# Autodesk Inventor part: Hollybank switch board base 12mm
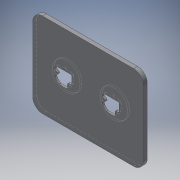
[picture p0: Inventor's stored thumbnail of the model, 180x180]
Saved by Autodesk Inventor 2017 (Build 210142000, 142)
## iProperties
Created: 2015-12
Part Number: Hollybank switch board base 12mm
Material: Generic
Document SubType Name: Modeling
Designer: Designer
Density: 1 g/cm^3
Appearance: Default
Author: Designer
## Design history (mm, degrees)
sketch "Sketch1"
  geometry: L1 (-57, 68.367)-(23, 68.367); L2 (33, 58.367)-(33, -21.633); L3 (23, -31.633)-(-57, -31.633); L4 (-67, -21.633)-(-67, 58.367); L5 (-5, -5)-(-5, 5.367); L6 (-2, 8.367)-(5, 8.367); L7 (8, 11.367)-(8, 33.367); L8 (-39.45, 36.367)-(5, 36.367); L9 (-36.434, 15.879)-(-43.759, 10.649); L10 (-36.443, 20.769)-(-43.792, 25.973); L11 (-40, 13.333)-(-40, 13.33); L12 (-30.528, -8)-(-8, -8); L13 (188, 148.367)-(-72, 148.367); L14 (-112, 108.367)-(-112, -71.633); L15 (-72, -111.633)-(188, -111.633); L16 (228, -71.633)-(228, 108.367); L17 (188, 148.367)-(228, 148.367); L18 (228, 108.367)-(228, 148.367); L19 (228, -71.633)-(228, -111.633); L20 (183, -111.633)-(228, -111.633); L21 (-72, -111.633)-(-112, -111.633); L22 (-112, -111.633)-(-112, -71.633); L23 (-72, 148.367)-(-112, 148.367); L24 (-112, 108.367)-(-112, 148.367); L25 (109.566, 15.879)-(102.241, 10.649); L26 (154, 11.367)-(154, 33.367); L27 (115.472, -8)-(138, -8); L28 (179, 58.367)-(179, -21.633); L29 (169, -31.633)-(89, -31.633); L30 (106, 13.333)-(106, 13.33); L31 (141, -5)-(141, 5.367); L32 (144, 8.367)-(151, 8.367); L33 (89, 68.367)-(169, 68.367); L34 (106.55, 36.367)-(151, 36.367); L35 (79, -21.633)-(79, 58.367); L36 (109.557, 20.769)-(102.208, 25.973); C1 r 1.5 at (-14.993, 41.367); C2 r 1.5 at (-40, 18.33); C3 r 1.5 at (0, 0); C4 r 1.5 at (106, 18.33); C5 r 1.5 at (146, 0); C6 r 1.5 at (131.007, 41.367); A1 r 30 centre (-17, 18.367) between (-41.944, 35.033) and (-44.842, 29.539); A2 r 30 centre (-17, 18.367) between (-44.795, 7.079) and (-32.031, -7.596); A3 r 10 centre (-57, 58.367) between (-57, 68.367) and (-67, 58.367); A4 r 10 centre (23, 58.367) between (33, 58.367) and (23, 68.367); A5 r 10 centre (23, -21.633) between (23, -31.633) and (33, -21.633); A6 r 10 centre (-57, -21.633) between (-67, -21.633) and (-57, -31.633); A7 r 3 centre (-38.177, 18.321) between (-36.434, 15.879) and (-36.443, 20.769); A8 r 3 centre (5, 11.367) between (5, 8.367) and (8, 11.367); A9 r 3 centre (-2, 5.367) between (-2, 8.367) and (-5, 5.367); A10 r 3 centre (-8, -5) between (-8, -8) and (-5, -5); A11 r 3 centre (-42.016, 8.208) between (-43.759, 10.649) and (-44.795, 7.079); A12 r 3 centre (-42.058, 28.422) between (-44.842, 29.539) and (-43.792, 25.973); A13 r 3 centre (-39.45, 33.367) between (-39.45, 36.367) and (-41.944, 35.033); A14 r 3 centre (-30.528, -5) between (-32.031, -7.596) and (-30.528, -8); A15 r 3 centre (5, 33.367) between (8, 33.367) and (5, 36.367); A16 r 30 centre (129, 18.367) between (101.205, 7.079) and (113.969, -7.596); A17 r 3 centre (138, -5) between (138, -8) and (141, -5); A18 r 3 centre (144, 5.367) between (144, 8.367) and (141, 5.367); A19 r 3 centre (151, 11.367) between (151, 8.367) and (154, 11.367); A20 r 10 centre (169, -21.633) between (169, -31.633) and (179, -21.633); A21 r 10 centre (89, -21.633) between (79, -21.633) and (89, -31.633); A22 r 3 centre (151, 33.367) between (154, 33.367) and (151, 36.367); A23 r 10 centre (169, 58.367) between (179, 58.367) and (169, 68.367); A24 r 10 centre (89, 58.367) between (89, 68.367) and (79, 58.367); A25 r 30 centre (129, 18.367) between (104.056, 35.033) and (101.158, 29.539); A26 r 3 centre (115.472, -5) between (113.969, -7.596) and (115.472, -8); A27 r 3 centre (103.984, 8.208) between (102.241, 10.649) and (101.205, 7.079); A28 r 3 centre (107.823, 18.321) between (109.566, 15.879) and (109.557, 20.769); A29 r 3 centre (103.942, 28.422) between (101.158, 29.539) and (102.208, 25.973); A30 r 3 centre (106.55, 33.367) between (106.55, 36.367) and (104.056, 35.033); 24 further points
  constraints: 72 end point, 68 point on circle, 48 tangent, 46 point on line, 36 centre point, 18 equal radius, 16 perpendicular, 7 equal length, 4 horizontal, 2 coincident
  dimensions: "d4" = 3 diameter of C2; "d5" = 3 diameter of C1; "d7" = 100 distance of point (-67, -31.633) point (-67, 68.367); "d8" = 100 distance of point (-67, 68.367) point (33, 68.367); "d17" = 5 distance from line of point (0, 0) L5; "d19" = 25 distance between parallel lines of L2 L7; "d23" = 34 distance of C1.centre C2.centre; "d24" = 44 distance of C1.centre C3.centre; "d25" = 44 distance of point (0, 0) C2.centre; "d26" = 32 distance between parallel lines of L8 L1; "d27" = 47.99344 distance from line of L2 C1.centre; "d28" = 33 distance from line of L2 point (0, 0); "d29" = 27 distance from line of C2.centre L4 (derived); "d30" = 49.96369 distance from line of L3 C2.centre; "d31" = 31.63338 distance from line of L3 C3.centre (derived); "d32" = 30 radius of A2; "d33" = 30 radius of A1; "d34" = 41 distance from line of L7 point (-33, 18.33); "d35" = 8 distance from line of L12 point (0, 0); "d36" = 23.63338 distance between parallel lines of L3 L12 (derived); "d37" = 10 radius of A3; "d40" = 3 radius of A7; "d41" = 3 radius of A8; "d42" = 3 radius of A15; "d61" = 24.98415 distance from line of L4 A11.centre; "d62" = 39.84089 distance from line of L3 A11.centre; "d63" = 28.82318 distance from line of L4 A7.centre; "d64" = 49.95389 distance from line of L3 A7.centre; "d65" = 27.55006 distance from line of L4 A13.centre; "d66" = 28 distance from line of L2 A15.centre; "d67" = 35 distance from line of A15.centre L1; "d68" = 3 diameter of C3; "d69" = 340 distance of L17.end L23.end; "d70" = 260 distance of L19.end L17.end; "d72" = 45 distance between parallel lines of L14 L4; "d117" = 28 distance from line of L2 A8.centre (derived); "d118" = 43 distance from line of L3 A8.centre; "d119" = 3 diameter of C4; "d120" = 3 diameter of C6; "d121" = 100 distance of point (79, -31.633) point (79, 68.367); "d122" = 100 distance of point (79, 68.367) point (179, 68.367); "d123" = 5 distance from line of point (146, 0) L31; "d124" = 25 distance between parallel lines of L28 L26; "d125" = 34 distance of C6.centre C4.centre; "d126" = 44 distance of C6.centre C5.centre; "d127" = 44 distance of point (146, 0) C4.centre; "d128" = 32 distance between parallel lines of L34 L33; "d129" = 47.99344 distance from line of L28 C6.centre; "d130" = 33 distance from line of L28 point (146, 0); "d131" = 27 distance from line of C4.centre L35 (derived); "d132" = 49.96369 distance from line of L29 C4.centre; "d133" = 31.63338 distance from line of L29 C5.centre (derived); "d134" = 30 radius of A16; "d135" = 30 radius of A25; "d136" = 41 distance from line of L26 point (113, 18.33); "d137" = 8 distance from line of L27 point (146, 0); "d138" = 23.63338 distance between parallel lines of L29 L27 (derived); "d139" = 10 radius of A24; "d140" = 3 radius of A28; "d141" = 3 radius of A19; "d142" = 3 radius of A22; "d143" = 24.98415 distance from line of L35 A27.centre; "d144" = 39.84089 distance from line of L29 A27.centre; "d145" = 28.82318 distance from line of L35 A28.centre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
extrude "Extrusion10" new body sketch "Sketch1" distance "d161" = 30; taper "d162" = 0 deg
sketch "Sketch6"
  geometry: L1 (-131.007, 41.367)-(-131.007, 10.217); L2 (14.993, 41.367)-(14.993, 11.919); L3 (112, 148.367)-(112, -111.633) reference; L4 (-131.007, 18.33)-(40, 18.33); C1 r 1.5 at (-131.007, 41.367) reference; C2 r 1.5 at (14.993, 41.367) reference; C3 r 1.5 at (40, 18.33) reference; C4 r 42.5 at (-131.007, 18.33); C5 r 42.5 at (14.993, 18.33); 1 further point
  constraints: 6 end point, 3 point on line, 2 centre point, 2 vertical, 1 coincident, 1 horizontal
  dimensions: "d164" = 85 diameter of C4; "d165" = 85 diameter of C5
extrude "Extrusion11" cut sketch "Sketch6" distance "d166" = 24; taper "d167" = 0 deg
fillet "Fillet1" dims "d168" = 30
sketch "Sketch7"
  geometry: L1 (324.857, -2)-(-75.143, -2); L2 (-75.143, -2)-(-75.143, 18); L3 (-75.143, 18)-(324.857, 18); L4 (324.857, 18)-(324.857, -2); L5 (0, 30)-(280, 30) reference; 1 further point
  constraints: 8 end point, 2 parallel, 1 horizontal, 1 perpendicular
  dimensions: "d169" = 20 distance of L3.end L1.start; "d170" = 400 distance of L1.start L1.end; "d171" = 12 distance between parallel lines of L5 L3
extrude "Extrusion12" cut sketch "Sketch7" stored distance "d172" = 24; taper "d173" = 0 deg
body "Solid4"
other parameters: "d15" = 32, "d16" = 25
